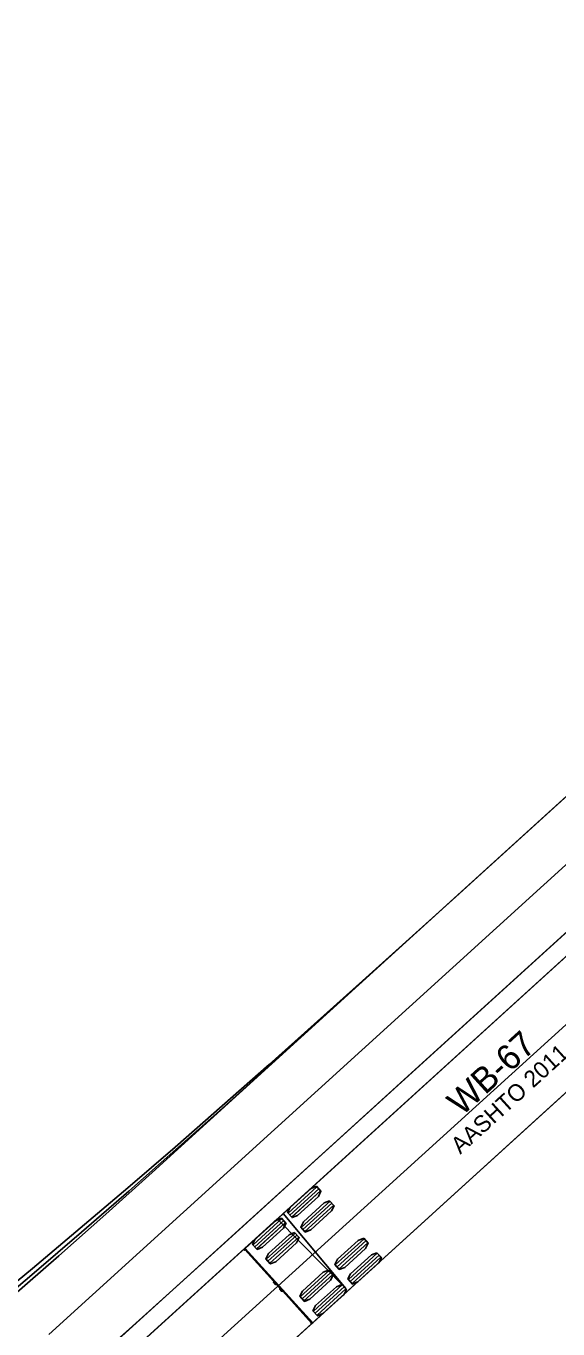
# Model space of a CAD drawing. Extents: x 1639988 to 1641860, y 841974 to 844187.
# Drawn here: x 1640698.9 to 1640743.9, y 844039.6 to 844149.7 of the extents above; entities that cross this region are included whole.
import ezdxf

# ---------------------------------------------------------------- set-up
doc = ezdxf.new("R2010")
doc.units = 0
for name, color, linetype in [('Scratch_Level_1', 7, 'Continuous'), ('Scratch_Level_2', 7, 'Continuous'), ('Scratch_Level_3', 7, 'Continuous'), ('Scratch_Level_4', 7, 'Continuous'), ('Scratch_Level_5', 7, 'Continuous'), ('Scratch_Level_6', 7, 'Continuous')]:
    doc.layers.add(name, color=color, linetype=linetype)

msp = doc.modelspace()

# ---------------------------------------------------------------- linework, layer by layer
at = {"layer": 'Scratch_Level_1'}
for p, q in [((1640767.68, 844099.85), (1640700.82, 844039.11)), ((1640606.39, 843939.82), (1640771.59, 844089.89)), ((1640723.49, 844051.6), (1640721.05, 844049.38)), ((1640723.64, 844051.43), (1640721.2, 844049.21)), ((1640723.8, 844051.26), (1640721.36, 844049.04)), ((1640724.6, 844050.38), (1640722.16, 844048.16)), ((1640724.75, 844050.21), (1640722.31, 844047.99)), ((1640724.91, 844050.04), (1640722.47, 844047.82)), ((1640720.53, 844048.91), (1640718.09, 844046.69)), ((1640720.68, 844048.74), (1640718.24, 844046.52)), ((1640720.84, 844048.57), (1640718.4, 844046.35)), ((1640721.64, 844047.69), (1640719.2, 844045.47)), ((1640721.79, 844047.52), (1640719.35, 844045.3)), ((1640721.95, 844047.35), (1640719.51, 844045.13)), ((1640727.48, 844047.21), (1640725.04, 844044.99)), ((1640727.63, 844047.04), (1640725.19, 844044.82)), ((1640727.79, 844046.87), (1640725.35, 844044.65)), ((1640723.13, 844040.09), (1640717.41, 844046.38)), ((1640728.59, 844045.99), (1640726.15, 844043.77)), ((1640728.74, 844045.82), (1640726.3, 844043.6)), ((1640728.9, 844045.65), (1640726.46, 844043.43)), ((1640724.52, 844044.52), (1640722.08, 844042.3)), ((1640720.04, 844043.38), (1640719.86, 844043.58)), ((1640724.67, 844044.35), (1640722.23, 844042.13)), ((1640724.83, 844044.18), (1640722.39, 844041.96)), ((1640720.22, 844043.19), (1640720.27, 844043.23)), ((1640720.57, 844042.79), (1640720.39, 844042.99)), ((1640725.63, 844043.3), (1640723.19, 844041.08)), ((1640725.78, 844043.13), (1640723.34, 844040.91)), ((1640725.94, 844042.96), (1640723.5, 844040.74))]:
    msp.add_line(p, q, dxfattribs=at)
for points in [[(1640691.49, 844037.55), (1640695.55, 844040.92), (1640699.58, 844044.33), (1640703.59, 844047.77), (1640707.58, 844051.24), (1640711.55, 844054.74), (1640715.5, 844058.26), (1640723.39, 844065.37), (1640803.32, 844137.96), (1640809.03, 844131.66), (1640808.79, 844131.45), (1640808.79, 844131.45)], [(1640808.79, 844131.45), (1640706.37, 844038.42), (1640702.38, 844034.84), (1640698.36, 844031.3), (1640694.3, 844027.8), (1640690.2, 844024.35), (1640686.05, 844020.94), (1640681.86, 844017.59), (1640677.63, 844014.29), (1640673.35, 844011.06), (1640669.03, 844007.88), (1640664.67, 844004.76), (1640660.28, 844001.71), (1640655.84, 843998.71), (1640651.39, 843995.75), (1640642.44, 843989.91), (1640624.5, 843978.33)], [(1640625.14, 843962.66), (1640720.12, 844048.88), (1640725.92, 844043), (1640720.62, 844049.33), (1640756.52, 844081.94), (1640756.91, 844081.96), (1640771.86, 844095.54), (1640777.24, 844089.62), (1640762.29, 844076.04), (1640762.24, 844075.65), (1640699.25, 844018.37), (1640667.74, 843989.65), (1640652.02, 843975.26), (1640636.33, 843960.85), (1640628.5, 843953.62)], [(1640723.06, 844040.06), (1640723.07, 844040.04), (1640723.13, 844040.09), (1640727.32, 844043.9), (1640762.24, 844075.65), (1640759.38, 844078.79), (1640756.52, 844081.94), (1640721.6, 844050.19), (1640717.41, 844046.38), (1640717.36, 844046.33), (1640717.37, 844046.31)], [(1640717.39, 844046.3), (1640717.39, 844046.3), (1640719.83, 844043.61), (1640719.86, 844043.58), (1640719.81, 844043.53), (1640719.81, 844043.53), (1640719.99, 844043.33)], [(1640720.04, 844043.38), (1640720.39, 844042.99)], [(1640720.34, 844042.94), (1640720.52, 844042.75), (1640720.52, 844042.75), (1640720.57, 844042.79), (1640720.6, 844042.77), (1640723.04, 844040.08), (1640723.04, 844040.08)]]:
    msp.add_lwpolyline(points, dxfattribs=at)
for points in [[(1640723.45, 844051.64), (1640723.83, 844051.22), (1640723.61, 844050.78), (1640721.85, 844049.18), (1640721.39, 844049), (1640721.01, 844049.42), (1640721.23, 844049.86), (1640722.99, 844051.46)], [(1640724.56, 844050.42), (1640724.95, 844049.99), (1640724.72, 844049.56), (1640722.96, 844047.96), (1640722.5, 844047.77), (1640722.12, 844048.2), (1640722.34, 844048.64), (1640724.1, 844050.23)], [(1640720.49, 844048.95), (1640720.88, 844048.52), (1640720.65, 844048.09), (1640718.89, 844046.49), (1640718.43, 844046.3), (1640718.05, 844046.73), (1640718.27, 844047.17), (1640720.03, 844048.76)], [(1640721.6, 844047.73), (1640721.99, 844047.3), (1640721.76, 844046.87), (1640720, 844045.27), (1640719.54, 844045.08), (1640719.16, 844045.51), (1640719.38, 844045.95), (1640721.14, 844047.54)], [(1640727.44, 844047.25), (1640727.83, 844046.83), (1640727.6, 844046.39), (1640725.84, 844044.79), (1640725.38, 844044.61), (1640725, 844045.03), (1640725.23, 844045.47), (1640726.98, 844047.07)], [(1640728.55, 844046.03), (1640728.94, 844045.6), (1640728.71, 844045.17), (1640726.95, 844043.57), (1640726.49, 844043.38), (1640726.11, 844043.81), (1640726.34, 844044.25), (1640728.09, 844045.84)], [(1640724.48, 844044.56), (1640724.87, 844044.13), (1640724.64, 844043.7), (1640722.88, 844042.1), (1640722.43, 844041.91), (1640722.04, 844042.34), (1640722.27, 844042.78), (1640724.02, 844044.37)], [(1640725.59, 844043.34), (1640725.98, 844042.91), (1640725.75, 844042.48), (1640723.99, 844040.88), (1640723.54, 844040.69), (1640723.15, 844041.12), (1640723.38, 844041.56), (1640725.13, 844043.15)]]:
    msp.add_lwpolyline(points, close=True, dxfattribs=at)
for centre in [(1640717.35, 844046.28), (1640723.03, 844040.04)]:
    msp.add_circle(centre, 0.0266, dxfattribs=at)
for centre, radius, start, end in [((1640717.35, 844046.28), 0.0363, 61.3558, 22.5172), ((1640720.01, 844043.36), 0.0353, 45.6145, 223.9642), ((1640720.01, 844043.36), 0.0352, 222.3036, 41.304), ((1640720.37, 844042.97), 0.0352, 43.2527, 222.2531), ((1640720.37, 844042.97), 0.0354, 226.5699, 38.7554), ((1640721.56, 844038.7), 2.02, 42.2784, 42.9621)]:
    msp.add_arc(centre, radius, start, end, dxfattribs=at)
at = {"layer": 'Scratch_Level_2'}
for p, q in [((1640767.68, 844099.85), (1640700.82, 844039.11)), ((1640606.39, 843939.82), (1640771.59, 844089.89))]:
    msp.add_line(p, q, dxfattribs=at)
for points in [[(1640691.27, 844038.02), (1640695.36, 844041.34), (1640699.43, 844044.7), (1640703.47, 844048.09), (1640707.49, 844051.51), (1640711.49, 844054.96), (1640715.48, 844058.44), (1640719.45, 844061.94), (1640727.35, 844069), (1640735.24, 844076.12), (1640816.27, 844149.72), (1640821.99, 844143.43), (1640821.87, 844143.33), (1640821.87, 844143.33)], [(1640821.87, 844143.33), (1640711.58, 844043.15), (1640707.6, 844039.57), (1640703.61, 844036.02), (1640699.58, 844032.49), (1640693.5, 844027.23), (1640689.41, 844023.77), (1640685.27, 844020.37), (1640681.07, 844017.03), (1640676.84, 844013.74), (1640672.56, 844010.52), (1640668.24, 844007.36), (1640663.87, 844004.26), (1640659.47, 844001.22), (1640655.02, 843998.24), (1640650.54, 843995.33), (1640648.28, 843993.89), (1640639.35, 843988.02), (1640630.41, 843982.19), (1640612.5, 843970.59)]]:
    msp.add_lwpolyline(points, dxfattribs=at)
at = {"layer": 'Scratch_Level_3'}
for p, q in [((1640767.68, 844099.85), (1640700.82, 844039.11)), ((1640606.39, 843939.82), (1640771.59, 844089.89)), ((1640723.49, 844051.6), (1640721.05, 844049.38)), ((1640723.64, 844051.43), (1640721.2, 844049.21)), ((1640723.8, 844051.26), (1640721.35, 844049.04)), ((1640724.6, 844050.38), (1640722.16, 844048.16)), ((1640724.75, 844050.21), (1640722.31, 844047.99)), ((1640724.91, 844050.04), (1640722.46, 844047.82)), ((1640720.53, 844048.91), (1640718.09, 844046.69)), ((1640720.68, 844048.74), (1640718.24, 844046.52)), ((1640720.84, 844048.57), (1640718.39, 844046.35)), ((1640721.64, 844047.69), (1640719.2, 844045.47)), ((1640721.79, 844047.52), (1640719.35, 844045.3)), ((1640721.95, 844047.35), (1640719.5, 844045.13)), ((1640727.48, 844047.21), (1640725.04, 844044.99)), ((1640727.63, 844047.04), (1640725.19, 844044.82)), ((1640727.79, 844046.87), (1640725.35, 844044.65)), ((1640723.13, 844040.09), (1640717.41, 844046.38)), ((1640728.59, 844045.99), (1640726.15, 844043.77)), ((1640728.74, 844045.82), (1640726.3, 844043.6)), ((1640728.9, 844045.65), (1640726.46, 844043.43)), ((1640724.52, 844044.52), (1640722.08, 844042.3)), ((1640720.04, 844043.38), (1640719.86, 844043.58)), ((1640724.67, 844044.35), (1640722.23, 844042.13)), ((1640724.83, 844044.18), (1640722.39, 844041.96)), ((1640720.21, 844043.19), (1640720.27, 844043.24)), ((1640720.57, 844042.79), (1640720.39, 844042.99)), ((1640725.63, 844043.3), (1640723.19, 844041.08)), ((1640725.78, 844043.13), (1640723.34, 844040.91)), ((1640725.94, 844042.96), (1640723.5, 844040.74))]:
    msp.add_line(p, q, dxfattribs=at)
for points in [[(1640691.27, 844038.02), (1640695.36, 844041.34), (1640699.43, 844044.7), (1640703.47, 844048.09), (1640707.49, 844051.51), (1640711.49, 844054.96), (1640715.48, 844058.44), (1640719.45, 844061.94), (1640727.35, 844069), (1640735.24, 844076.12), (1640816.27, 844149.72), (1640821.99, 844143.43), (1640821.88, 844143.33), (1640821.88, 844143.33)], [(1640821.88, 844143.33), (1640711.58, 844043.15), (1640707.6, 844039.57), (1640703.61, 844036.02), (1640699.58, 844032.49), (1640693.5, 844027.23), (1640689.41, 844023.77), (1640685.27, 844020.37), (1640681.07, 844017.03), (1640676.84, 844013.74), (1640672.56, 844010.52), (1640668.24, 844007.36), (1640663.87, 844004.26), (1640659.47, 844001.22), (1640655.02, 843998.24), (1640650.54, 843995.33), (1640648.28, 843993.89), (1640639.35, 843988.02), (1640630.41, 843982.19), (1640612.5, 843970.59)], [(1640617.99, 843956.15), (1640720.12, 844048.88), (1640725.92, 844043), (1640720.62, 844049.33), (1640756.52, 844081.94), (1640756.91, 844081.96), (1640771.86, 844095.54), (1640777.24, 844089.61), (1640762.29, 844076.04), (1640762.24, 844075.65), (1640699, 844018.14), (1640667.49, 843989.43), (1640651.76, 843975.05), (1640636.06, 843960.64), (1640620.41, 843946.19)], [(1640723.06, 844040.06), (1640723.07, 844040.04), (1640723.13, 844040.09), (1640727.32, 844043.9), (1640762.24, 844075.65), (1640759.38, 844078.79), (1640756.52, 844081.94), (1640721.6, 844050.19), (1640717.41, 844046.38), (1640717.36, 844046.33), (1640717.37, 844046.32)], [(1640717.39, 844046.3), (1640717.39, 844046.3), (1640719.83, 844043.61), (1640719.86, 844043.58), (1640719.81, 844043.53), (1640719.81, 844043.53), (1640719.99, 844043.33)], [(1640720.04, 844043.38), (1640720.39, 844042.99)], [(1640720.34, 844042.95), (1640720.52, 844042.75), (1640720.52, 844042.75), (1640720.57, 844042.79), (1640720.6, 844042.77), (1640723.04, 844040.08), (1640723.04, 844040.08)]]:
    msp.add_lwpolyline(points, dxfattribs=at)
for points in [[(1640723.45, 844051.64), (1640723.83, 844051.22), (1640723.61, 844050.78), (1640721.85, 844049.18), (1640721.39, 844049), (1640721.01, 844049.42), (1640721.23, 844049.86), (1640722.99, 844051.46)], [(1640724.56, 844050.42), (1640724.94, 844050), (1640724.72, 844049.56), (1640722.96, 844047.96), (1640722.5, 844047.78), (1640722.12, 844048.2), (1640722.34, 844048.64), (1640724.1, 844050.24)], [(1640720.49, 844048.95), (1640720.87, 844048.53), (1640720.65, 844048.09), (1640718.89, 844046.49), (1640718.43, 844046.31), (1640718.05, 844046.73), (1640718.27, 844047.17), (1640720.03, 844048.77)], [(1640721.6, 844047.73), (1640721.98, 844047.31), (1640721.76, 844046.87), (1640720, 844045.27), (1640719.54, 844045.09), (1640719.16, 844045.51), (1640719.38, 844045.95), (1640721.14, 844047.55)], [(1640727.44, 844047.25), (1640727.83, 844046.83), (1640727.6, 844046.39), (1640725.84, 844044.79), (1640725.38, 844044.61), (1640725, 844045.03), (1640725.22, 844045.47), (1640726.98, 844047.07)], [(1640728.55, 844046.03), (1640728.94, 844045.61), (1640728.71, 844045.17), (1640726.95, 844043.57), (1640726.49, 844043.39), (1640726.11, 844043.81), (1640726.33, 844044.25), (1640728.09, 844045.85)], [(1640724.48, 844044.56), (1640724.87, 844044.14), (1640724.64, 844043.7), (1640722.88, 844042.1), (1640722.42, 844041.92), (1640722.04, 844042.34), (1640722.27, 844042.78), (1640724.02, 844044.38)], [(1640725.59, 844043.34), (1640725.98, 844042.91), (1640725.75, 844042.48), (1640723.99, 844040.88), (1640723.53, 844040.7), (1640723.15, 844041.12), (1640723.38, 844041.56), (1640725.13, 844043.15)]]:
    msp.add_lwpolyline(points, close=True, dxfattribs=at)
for centre in [(1640717.35, 844046.28), (1640723.03, 844040.05)]:
    msp.add_circle(centre, 0.0266, dxfattribs=at)
for centre, radius, start, end in [((1640717.35, 844046.28), 0.0363, 61.3538, 22.5152), ((1640720.01, 844043.36), 0.0353, 45.6126, 223.9622), ((1640720.01, 844043.36), 0.0352, 222.3017, 41.3021), ((1640720.37, 844042.97), 0.0352, 43.2507, 222.2511), ((1640720.37, 844042.97), 0.0354, 226.5679, 38.7534), ((1640721.56, 844038.7), 2.02, 42.2764, 42.9602)]:
    msp.add_arc(centre, radius, start, end, dxfattribs=at)
at = {"layer": 'Scratch_Level_4'}
for p, q in [((1640767.68, 844099.85), (1640700.82, 844039.11)), ((1640606.39, 843939.82), (1640771.59, 844089.89))]:
    msp.add_line(p, q, dxfattribs=at)
for points in [[(1640629.66, 843992.17), (1640638.52, 843998.05), (1640642.93, 844001), (1640647.33, 844003.97), (1640651.71, 844006.96), (1640656.07, 844009.97), (1640660.4, 844013), (1640664.69, 844016.07), (1640668.95, 844019.18), (1640673.16, 844022.34), (1640677.33, 844025.54), (1640681.47, 844028.8), (1640685.57, 844032.11), (1640689.64, 844035.46), (1640693.68, 844038.86), (1640697.68, 844042.3), (1640701.67, 844045.77), (1640705.63, 844049.28), (1640709.57, 844052.82), (1640789.25, 844125.18), (1640794.97, 844118.89), (1640794.76, 844118.7), (1640794.76, 844118.7)], [(1640794.76, 844118.7), (1640731.8, 844061.51), (1640716.02, 844047.15), (1640708.1, 844039.98), (1640700.16, 844032.77), (1640696.18, 844029.18), (1640694.17, 844027.4), (1640692.14, 844025.64), (1640690.1, 844023.9), (1640688.04, 844022.17), (1640685.97, 844020.45), (1640683.89, 844018.76), (1640681.79, 844017.07), (1640677.56, 844013.76), (1640673.28, 844010.5), (1640668.95, 844007.31), (1640664.59, 844004.18), (1640660.18, 844001.12), (1640655.74, 843998.13), (1640651.26, 843995.2), (1640646.75, 843992.33), (1640637.7, 843986.65), (1640628.69, 843980.93)], [(1640624.43, 843962.03), (1640656.03, 843990.67), (1640773.92, 844097.74), (1640779.63, 844091.45), (1640653.14, 843976.52), (1640637.37, 843962.18), (1640621.63, 843947.81)]]:
    msp.add_lwpolyline(points, dxfattribs=at)
at = {"layer": 'Scratch_Level_5'}
for p, q in [((1640767.68, 844099.85), (1640700.82, 844039.11)), ((1640606.39, 843939.82), (1640771.59, 844089.89))]:
    msp.add_line(p, q, dxfattribs=at)
for points in [[(1640629.66, 843992.17), (1640638.52, 843998.05), (1640642.93, 844001), (1640647.33, 844003.97), (1640651.71, 844006.96), (1640656.07, 844009.97), (1640660.4, 844013), (1640664.69, 844016.07), (1640668.95, 844019.18), (1640673.16, 844022.34), (1640677.33, 844025.54), (1640681.47, 844028.8), (1640685.57, 844032.11), (1640689.64, 844035.46), (1640693.68, 844038.86), (1640697.68, 844042.3), (1640701.67, 844045.77), (1640705.63, 844049.28), (1640709.57, 844052.82), (1640789.25, 844125.18), (1640794.97, 844118.89)], [(1640794.75, 844118.69), (1640731.8, 844061.51), (1640716.02, 844047.15), (1640708.1, 844039.98), (1640700.16, 844032.77), (1640696.18, 844029.18), (1640694.17, 844027.4), (1640692.14, 844025.64), (1640690.1, 844023.9), (1640688.04, 844022.17), (1640685.97, 844020.45), (1640683.89, 844018.76), (1640681.79, 844017.07), (1640677.56, 844013.76), (1640673.28, 844010.5), (1640668.95, 844007.31), (1640664.59, 844004.18), (1640660.18, 844001.12), (1640655.74, 843998.13), (1640651.26, 843995.2), (1640646.75, 843992.33), (1640637.7, 843986.65), (1640628.69, 843980.93)], [(1640624.43, 843962.03), (1640656.03, 843990.67), (1640773.92, 844097.74), (1640779.63, 844091.45), (1640653.14, 843976.52), (1640637.37, 843962.18), (1640621.63, 843947.81)]]:
    msp.add_lwpolyline(points, dxfattribs=at)
at = {"layer": 'Scratch_Level_6'}
for p, q in [((1640767.68, 844099.85), (1640700.82, 844039.11)), ((1640606.39, 843939.82), (1640771.59, 844089.89))]:
    msp.add_line(p, q, dxfattribs=at)
for points in [[(1640629.66, 843992.17), (1640638.52, 843998.05), (1640642.93, 844001), (1640647.33, 844003.97), (1640651.71, 844006.96), (1640656.07, 844009.97), (1640660.4, 844013), (1640664.69, 844016.07), (1640668.95, 844019.18), (1640673.16, 844022.34), (1640677.33, 844025.54), (1640681.47, 844028.8), (1640685.57, 844032.11), (1640689.64, 844035.46), (1640693.68, 844038.86), (1640697.68, 844042.3), (1640701.67, 844045.77), (1640705.63, 844049.28), (1640709.57, 844052.82), (1640789.25, 844125.18), (1640794.97, 844118.89), (1640794.78, 844118.72), (1640794.78, 844118.72)], [(1640794.78, 844118.72), (1640731.8, 844061.51), (1640716.02, 844047.15), (1640708.1, 844039.98), (1640700.16, 844032.77), (1640696.18, 844029.18), (1640694.17, 844027.4), (1640692.14, 844025.64), (1640690.1, 844023.9), (1640688.04, 844022.17), (1640685.97, 844020.45), (1640683.89, 844018.76), (1640681.79, 844017.07), (1640677.56, 844013.76), (1640673.28, 844010.5), (1640668.95, 844007.31), (1640664.59, 844004.18), (1640660.18, 844001.12), (1640655.74, 843998.13), (1640651.26, 843995.2), (1640646.75, 843992.33), (1640637.7, 843986.65), (1640628.69, 843980.93)], [(1640624.19, 843961.81), (1640655.78, 843990.45), (1640773.92, 844097.74), (1640779.63, 844091.45), (1640653.14, 843976.52), (1640637.37, 843962.18), (1640621.63, 843947.81)]]:
    msp.add_lwpolyline(points, dxfattribs=at)

# ---------------------------------------------------------------- texts
at = {"layer": 'Scratch_Level_1'}
for s, height, p in [('AASHTO 2011 (US)', 1.4167, (1640735.61, 844054.3)), ('WB-67', 2.125, (1640735.73, 844057.52)), ('(c) 2019 Transoft Solutions, Inc. All rights reserved.', 0.085, (1640738.52, 844059.77))]:
    msp.add_text(s, height=height, rotation=42.2784, dxfattribs=at).set_placement(p)
at = {"layer": 'Scratch_Level_3'}
for s, height, p in [('AASHTO 2011 (US)', 1.4167, (1640735.61, 844054.3)), ('WB-67', 2.125, (1640735.72, 844057.52)), ('(c) 2019 Transoft Solutions, Inc. All rights reserved.', 0.085, (1640738.52, 844059.77))]:
    msp.add_text(s, height=height, rotation=42.2764, dxfattribs=at).set_placement(p)

doc.saveas('drawing.dxf')
